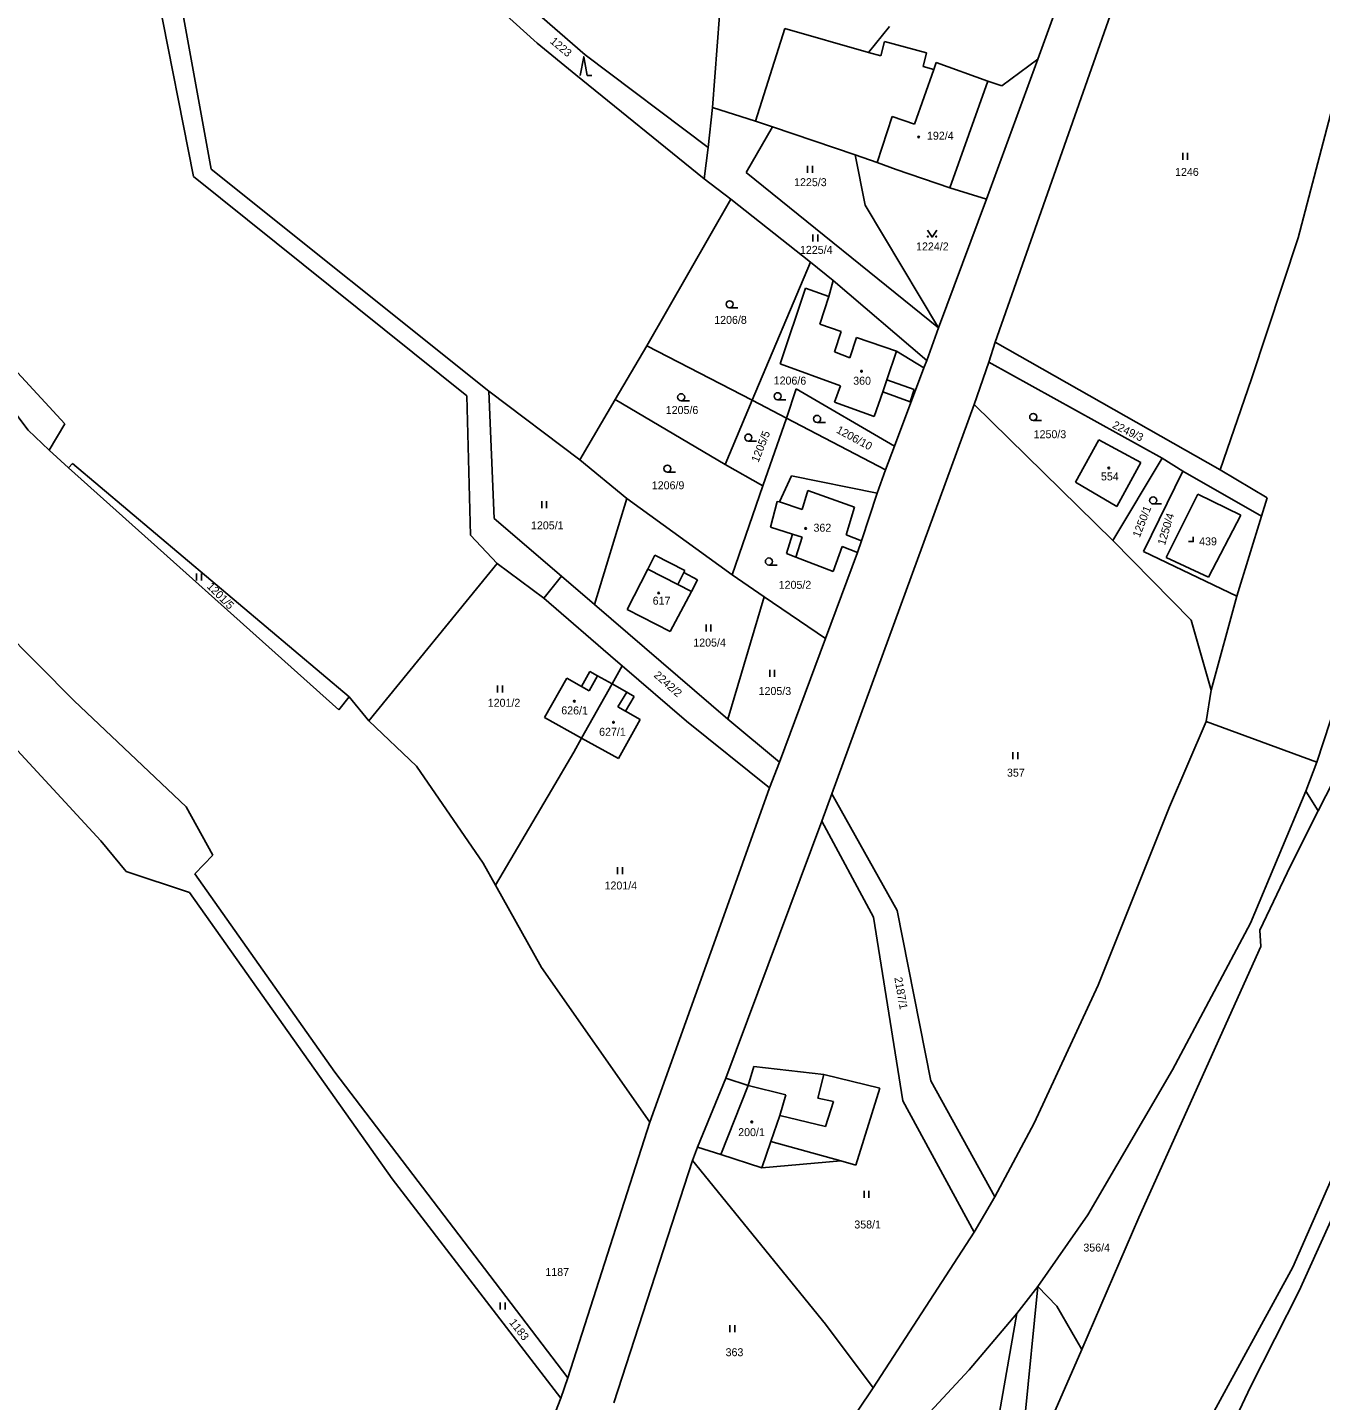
# Model space of a CAD drawing. Extents: x -717507 to -715515, y -957700 to -954941.
# Drawn here: x -717129.5 to -716853.4, y -957227.8 to -956934.7 of the extents above; entities that cross this region are included whole.
import ezdxf

# ---------------------------------------------------------------- set-up
doc = ezdxf.new("R2010")
doc.units = 0
for name, color, linetype in [('Hranice parcel', 7, 'Continuous'), ('Parcelní čísla', 7, 'Continuous'), ('Vnitřní kresba', 7, 'Continuous'), ('Značky budov', 7, 'Continuous'), ('Značky kultur', 7, 'Continuous')]:
    doc.layers.add(name, color=color, linetype=linetype)

msp = doc.modelspace()

# ---------------------------------------------------------------- linework, layer by layer
at = {"layer": 'Hranice parcel'}
for points in [[(-716883.47, -956889.98), (-716922.85, -957001.88)], [(-716899.47, -956902.24), (-716913.71, -956941.41)], [(-717040.64, -956914.21), (-717010.38, -956940.53)], [(-717020.68, -956938), (-717043.43, -956917.39)], [(-717090.31, -956964.95), (-717097.11, -956927.29)], [(-716983.22, -956951.73), (-716981.19, -956925.52)], [(-717101.64, -956927.88), (-717094.06, -956966.51)], [(-716967.79, -956934.88), (-716974.01, -956954.65)], [(-716967.79, -956934.88), (-716949.89, -956940.04)], [(-716949.89, -956940.04), (-716945.43, -956934.46)], [(-717012.39, -956944.75), (-717020.68, -956938)], [(-716946.46, -956937.68), (-716947.27, -956940.76)], [(-716946.46, -956937.68), (-716937.49, -956940.07)], [(-716984.16, -956960.33), (-717010.38, -956940.53)], [(-716949.89, -956940.04), (-716947.27, -956940.76)], [(-716937.49, -956940.07), (-716938.2, -956943.02)], [(-716924.72, -956971.35), (-716913.71, -956941.41)], [(-716913.71, -956941.41), (-716921.45, -956947.14)], [(-716985.03, -956966.96), (-717012.39, -956944.75)], [(-716938.2, -956943.02), (-716935.96, -956943.61)], [(-716935.48, -956942.18), (-716935.96, -956943.61)], [(-716935.48, -956942.18), (-716924.4, -956946.14)], [(-716924.4, -956946.14), (-716921.45, -956947.14)], [(-716849.73, -956947.55), (-716858.15, -956979.57)], [(-716983.22, -956951.73), (-716984.16, -956960.33)], [(-716983.22, -956951.73), (-716974.01, -956954.65)], [(-716976.05, -956965.65), (-716970.44, -956955.86)], [(-716974.01, -956954.65), (-716970.44, -956955.86)], [(-716970.44, -956955.86), (-716952.72, -956961.89)], [(-717175.29, -956959.79), (-717129.34, -957020.62)], [(-716984.16, -956960.33), (-716985.03, -956966.96)], [(-716952.72, -956961.89), (-716950.58, -956972.63)], [(-716952.72, -956961.89), (-716948.05, -956963.51)], [(-717031.01, -957012.35), (-717090.31, -956964.95)], [(-716948.05, -956963.51), (-716943.97, -956965)], [(-716943.97, -956965), (-716932.56, -956968.89)], [(-717094.06, -956966.51), (-717035.68, -957013.31)], [(-716985.03, -956966.96), (-716979.33, -956971.36)], [(-716934.96, -956998.81), (-716976.05, -956965.65)], [(-716997.26, -957002.63), (-716979.33, -956971.36)], [(-716979.33, -956971.36), (-716962.26, -956984.8)], [(-716924.72, -956971.35), (-716934.96, -956998.81)], [(-716932.56, -956968.89), (-716924.72, -956971.35)], [(-716934.96, -956998.81), (-716950.58, -956972.63)], [(-716858.15, -956979.57), (-716868.1, -957009.68)], [(-716962.26, -956984.8), (-716974.74, -957014.21)], [(-716962.26, -956984.8), (-716957.43, -956988.72)], [(-716958.39, -956992.1), (-716957.43, -956988.72)], [(-716957.43, -956988.72), (-716937.47, -957005.77)], [(-716963.33, -956990.31), (-716968.74, -957006.5)], [(-716963.33, -956990.31), (-716958.39, -956992.1)], [(-717121.57, -957019.32), (-717146.06, -956992.81)], [(-716934.96, -956998.81), (-716937.47, -957005.77)], [(-716997.26, -957002.63), (-717003.99, -957014.1)], [(-716997.26, -957002.63), (-716974.74, -957014.21)], [(-716922.85, -957001.88), (-716924.19, -957006.09)], [(-716922.85, -957001.88), (-716874.81, -957029.09)], [(-716968.74, -957006.5), (-716955.91, -957011.2)], [(-716943.95, -957003.75), (-716946, -957009.87)], [(-716938.06, -957007.35), (-716943.95, -957003.75)], [(-716937.47, -957005.77), (-716938.06, -957007.35)], [(-716924.19, -957006.09), (-716927.36, -957015.18)], [(-716924.19, -957006.09), (-716887.2, -957026.59)], [(-716938.06, -957007.35), (-716944.34, -957024.03)], [(-717011.58, -957027), (-717031.01, -957012.35)], [(-717029.86, -957039.5), (-717031.01, -957012.35)], [(-716965.34, -957011.84), (-716967.45, -957018.1)], [(-716944.34, -957024.03), (-716965.34, -957011.84)], [(-716955.91, -957011.2), (-716957.14, -957014.7)], [(-716946.87, -957012.44), (-716948.72, -957017.75)], [(-716946.87, -957012.44), (-716941.01, -957014.57)], [(-716946, -957009.87), (-716940.13, -957011.95)], [(-716940.13, -957011.95), (-716941.01, -957014.57)], [(-716874.81, -957029.09), (-716868.1, -957009.68)], [(-717035.68, -957013.31), (-717034.88, -957043.03)], [(-717003.99, -957014.1), (-717011.58, -957027)], [(-717003.99, -957014.1), (-716980.54, -957027.95)], [(-716974.74, -957014.21), (-716980.54, -957027.95)], [(-716974.74, -957014.21), (-716967.45, -957018.1)], [(-716927.36, -957015.18), (-716957.76, -957098.3)], [(-716957.14, -957014.7), (-716948.72, -957017.75)], [(-716927.36, -957015.18), (-716897.7, -957044.17)], [(-716967.45, -957018.1), (-716972.5, -957032.52)], [(-716967.45, -957018.1), (-716946.29, -957029.08)], [(-717124.87, -957024.92), (-717129.34, -957020.62)], [(-717121.57, -957019.32), (-717124.87, -957024.92)], [(-716944.34, -957024.03), (-716946.29, -957029.08)], [(-716900.69, -957022.74), (-716905.7, -957031.72)], [(-716900.69, -957022.74), (-716891.72, -957027.57)], [(-717120.72, -957028.71), (-717124.87, -957024.92)], [(-717001.53, -957035.23), (-717011.58, -957027)], [(-716887.2, -957026.59), (-716897.7, -957044.17)], [(-716887.2, -957026.59), (-716882.75, -957029.4)], [(-717120.72, -957028.71), (-717119.88, -957027.74)], [(-717062.99, -957080.37), (-717120.72, -957028.71)], [(-717060.78, -957077.58), (-717119.88, -957027.74)], [(-716980.54, -957027.95), (-716972.5, -957032.52)], [(-716946.29, -957029.08), (-716948.04, -957034.12)], [(-716891.72, -957027.57), (-716896.85, -957036.91)], [(-716882.75, -957029.4), (-716891.17, -957046.55)], [(-716882.75, -957029.4), (-716865.96, -957038.98)], [(-716874.81, -957029.09), (-716864.74, -957035.09)], [(-716972.5, -957032.52), (-716978.99, -957051.55)], [(-716966.38, -957030.36), (-716968.94, -957035.94)], [(-716966.38, -957030.36), (-716948.04, -957034.12)], [(-716905.7, -957031.72), (-716896.85, -957036.91)], [(-717008.45, -957057.86), (-717001.53, -957035.23)], [(-716978.99, -957051.55), (-717001.53, -957035.23)], [(-716969.39, -957035.84), (-716970.81, -957041.37)], [(-716969.39, -957035.84), (-716968.94, -957035.94)], [(-716948.04, -957034.12), (-716951.4, -957044.29)], [(-716879.57, -957034.34), (-716886.33, -957047.83)], [(-716879.57, -957034.34), (-716870.36, -957038.79)], [(-716864.74, -957035.09), (-716865.96, -957038.98)], [(-716870.36, -957038.79), (-716877.32, -957052.05)], [(-717015.46, -957051.8), (-717029.86, -957039.5)], [(-716970.81, -957041.37), (-716966.11, -957042.83)], [(-716865.96, -957038.98), (-716871.21, -957056.08)], [(-717034.88, -957043.03), (-717029.19, -957049.13)], [(-716966.11, -957042.83), (-716967.41, -957046.98)], [(-716951.4, -957044.29), (-716952.24, -957046.75)], [(-716897.7, -957044.17), (-716880.98, -957061.2)], [(-716995.51, -957047.35), (-716997.02, -957050.3)], [(-716995.51, -957047.35), (-716989.12, -957050.63)], [(-716967.41, -957046.98), (-716965.4, -957047.72)], [(-716952.24, -957046.75), (-716959.08, -957065.13)], [(-716955.52, -957045.49), (-716957.43, -957050.8)], [(-716955.52, -957045.49), (-716952.24, -957046.75)], [(-716891.17, -957046.55), (-716871.21, -957056.08)], [(-717029.19, -957049.13), (-717056.63, -957082.7)], [(-717029.19, -957049.13), (-717019.23, -957056.54)], [(-716997.02, -957050.3), (-717001.45, -957058.93)], [(-716965.4, -957047.72), (-716957.43, -957050.8)], [(-716886.33, -957047.83), (-716877.32, -957052.05)], [(-717018.6, -957055.75), (-717015.46, -957051.8)], [(-717008.45, -957057.86), (-717015.46, -957051.8)], [(-716989.12, -957050.63), (-716989.34, -957051.06)], [(-716989.34, -957051.06), (-716986.41, -957052.56)], [(-716986.41, -957052.56), (-716987.7, -957055.08)], [(-716972.18, -957056.21), (-716978.99, -957051.55)], [(-716854.19, -957091.5), (-716841.23, -957052.04)], [(-717119.57, -957078.45), (-717143.05, -957054.83)], [(-717018.6, -957055.75), (-717019.23, -957056.54)], [(-716987.7, -957055.08), (-716992.26, -957063.64)], [(-716979.94, -957082.35), (-716972.18, -957056.21)], [(-716959.08, -957065.13), (-716972.18, -957056.21)], [(-716871.21, -957056.08), (-716876.69, -957076.13)], [(-717019.23, -957056.54), (-717003.9, -957069.75)], [(-716979.94, -957082.35), (-717008.45, -957057.86)], [(-717001.45, -957058.93), (-716992.26, -957063.64)], [(-716876.69, -957076.13), (-716880.98, -957061.2)], [(-716959.08, -957065.13), (-716968.89, -957091.5)], [(-716834.54, -957064.04), (-716853.87, -957101.91)], [(-717002.5, -957070.96), (-717004.65, -957074.83)], [(-717003.9, -957069.75), (-717002.5, -957070.96)], [(-717002.5, -957070.96), (-716988.77, -957082.77)], [(-717014.35, -957073.57), (-717019.09, -957081.99)], [(-717011.18, -957075.35), (-717014.35, -957073.57)], [(-717009.41, -957072.18), (-717011.18, -957075.35)], [(-717007.79, -957073.08), (-717009.41, -957072.18)], [(-717007.79, -957073.08), (-717004.65, -957074.83)], [(-717004.65, -957074.83), (-717011.17, -957086.38)], [(-717001.54, -957076.57), (-717004.65, -957074.83)], [(-716999.92, -957077.47), (-717001.54, -957076.57)], [(-716876.69, -957076.13), (-716877.77, -957082.81)], [(-717095.65, -957101.03), (-717119.57, -957078.45)], [(-717060.78, -957077.58), (-717062.99, -957080.37)], [(-717060.78, -957077.58), (-717056.63, -957082.7)], [(-717001.79, -957080.62), (-716999.92, -957077.47)], [(-717046.43, -957092.34), (-717056.63, -957082.7)], [(-717019.09, -957081.99), (-717011.17, -957086.38)], [(-717003.27, -957090.76), (-716998.65, -957082.38)], [(-716998.65, -957082.38), (-717001.79, -957080.62)], [(-716988.77, -957082.77), (-716971.07, -957097)], [(-716968.89, -957091.5), (-716979.94, -957082.35)], [(-716877.77, -957082.81), (-716885.65, -957101.08)], [(-716877.77, -957082.81), (-716854.19, -957091.5)], [(-717136.81, -957083.48), (-717113.86, -957108.34)], [(-717011.17, -957086.38), (-717012.83, -957089.39)], [(-717011.17, -957086.38), (-717003.27, -957090.76)], [(-717012.83, -957089.39), (-717017.59, -957097.48)], [(-716971.07, -957097), (-716968.89, -957091.5)], [(-716856.5, -957097.71), (-716854.19, -957091.5)], [(-717046.43, -957092.34), (-717032.22, -957113.08)], [(-717017.59, -957097.48), (-717029.57, -957117.8)], [(-716982.61, -957129.3), (-716971.07, -957097)], [(-716957.76, -957098.3), (-716959.9, -957104.09)], [(-716957.76, -957098.3), (-716943.77, -957123.22)], [(-716868.32, -957125.9), (-716856.5, -957097.71)], [(-716853.87, -957101.91), (-716856.5, -957097.71)], [(-717095.65, -957101.03), (-717089.96, -957111.41)], [(-716900.87, -957139.14), (-716885.65, -957101.08)], [(-716853.87, -957101.91), (-716859.8, -957113.63)], [(-716959.9, -957104.09), (-716980.38, -957159)], [(-716959.9, -957104.09), (-716948.82, -957124.63)], [(-717108.43, -957114.88), (-717113.86, -957108.34)], [(-717089.96, -957111.41), (-717093.74, -957115.35)], [(-717108.43, -957114.88), (-717094.88, -957119.36)], [(-717032.22, -957113.08), (-717029.57, -957117.8)], [(-716859.8, -957113.63), (-716866.3, -957127.42)], [(-717093.74, -957115.35), (-717063.87, -957157.69)], [(-717019.75, -957135.34), (-717029.57, -957117.8)], [(-716859.27, -957199.3), (-716823.29, -957117.25)], [(-717094.88, -957119.36), (-717051.63, -957180.5)], [(-716943.77, -957123.22), (-716936.58, -957159.52)], [(-716948.82, -957124.63), (-716942.54, -957163.79)], [(-716884.96, -957157.2), (-716868.32, -957125.9)], [(-716996.57, -957168.36), (-716982.61, -957129.3)], [(-716866.3, -957127.42), (-716866.09, -957130.84)], [(-716823.97, -957129.29), (-716857.93, -957204.39)], [(-716866.09, -957130.84), (-716892.17, -957188.76)], [(-716996.57, -957168.36), (-717019.75, -957135.34)], [(-716900.87, -957139.14), (-716914.54, -957168.6)], [(-717014.14, -957222.99), (-717063.87, -957157.69)], [(-716980.38, -957159), (-716986.4, -957173.71)], [(-716980.38, -957159), (-716975.62, -957160.52)], [(-716974.36, -957156.51), (-716975.62, -957160.52)], [(-716974.36, -957156.51), (-716959.41, -957158.22)], [(-716947.51, -957161.09), (-716959.41, -957158.22)], [(-716903.08, -957188.17), (-716884.96, -957157.2)], [(-716947.51, -957161.09), (-716952.58, -957177.57)], [(-716922.9, -957184.34), (-716936.58, -957159.52)], [(-716927.37, -957191.86), (-716942.54, -957163.79)], [(-716996.57, -957168.36), (-717014.14, -957222.99)], [(-716914.54, -957168.6), (-716922.9, -957184.34)], [(-716986.4, -957173.71), (-716987.46, -957176.58)], [(-716986.4, -957173.71), (-716981.47, -957175.31)], [(-716987.46, -957176.58), (-717004.3, -957228.3)], [(-716987.46, -957176.58), (-716959.12, -957211.47)], [(-716981.47, -957175.31), (-716972.71, -957178.12)], [(-716972.71, -957178.12), (-716955.82, -957176.65)], [(-716955.82, -957176.65), (-716952.58, -957177.57)], [(-717051.63, -957180.5), (-717015.58, -957227.31)], [(-716922.9, -957184.34), (-716927.37, -957191.86)], [(-716903.08, -957188.17), (-716913.74, -957203.47)], [(-716892.17, -957188.76), (-716904.33, -957216.92)], [(-716927.37, -957191.86), (-716948.88, -957225.08)], [(-716859.27, -957199.3), (-716896.13, -957266.78)], [(-716913.74, -957203.47), (-716918.24, -957209.2)], [(-716913.74, -957203.47), (-716909.66, -957207.64)], [(-716868.3, -957224.89), (-716857.93, -957204.39)], [(-716904.33, -957216.92), (-716909.66, -957207.64)], [(-716948.88, -957225.08), (-716959.12, -957211.47)], [(-716918.24, -957209.2), (-716928.37, -957221.22)], [(-716918.24, -957209.2), (-716921.9, -957230.38)], [(-716904.33, -957216.92), (-716932.34, -957280.9)], [(-717014.14, -957222.99), (-717015.58, -957227.31)], [(-716972.18, -957268.34), (-716928.37, -957221.22)], [(-716961.32, -957243.51), (-716948.88, -957225.08)], [(-716883.16, -957256.29), (-716868.3, -957224.89)], [(-717042.82, -957297.1), (-717015.58, -957227.31)]]:
    msp.add_lwpolyline(points, dxfattribs=at)
at = {"layer": 'Vnitřní kresba'}
for points in [[(-716935.96, -956943.61), (-716940.05, -956955.34)], [(-716924.4, -956946.14), (-716932.56, -956968.89)], [(-716944.87, -956953.65), (-716948.05, -956963.51)], [(-716944.87, -956953.65), (-716940.05, -956955.34)], [(-716958.39, -956992.1), (-716960.28, -956998.02)], [(-716960.28, -956998.02), (-716955.72, -956999.57)], [(-716955.72, -956999.57), (-716957.14, -957003.95)], [(-716952.48, -957000.83), (-716953.87, -957005.18)], [(-716952.48, -957000.83), (-716943.95, -957003.75)], [(-716957.14, -957003.95), (-716953.87, -957005.18)], [(-716946, -957009.87), (-716946.87, -957012.44)], [(-716968.94, -957035.94), (-716964.1, -957037.61)], [(-716964.1, -957037.61), (-716962.84, -957033.5)], [(-716962.84, -957033.5), (-716952.89, -957037.06)], [(-716952.89, -957037.06), (-716954.67, -957043.02)], [(-716966.11, -957042.83), (-716964.1, -957043.51)], [(-716964.1, -957043.51), (-716965.4, -957047.72)], [(-716954.67, -957043.02), (-716951.4, -957044.29)], [(-716997.02, -957050.3), (-716990.63, -957053.58)], [(-716990.63, -957053.58), (-716989.34, -957051.06)], [(-716990.63, -957053.58), (-716987.7, -957055.08)], [(-717009.56, -957076.26), (-717007.79, -957073.08)], [(-717011.18, -957075.35), (-717009.56, -957076.26)], [(-717001.54, -957076.57), (-717003.41, -957079.71)], [(-717003.41, -957079.71), (-717001.79, -957080.62)], [(-716959.41, -957158.22), (-716960.69, -957163.23)], [(-716975.62, -957160.52), (-716981.47, -957175.31)], [(-716975.62, -957160.52), (-716967.53, -957162.56)], [(-716967.53, -957162.56), (-716968.87, -957166.95)], [(-716960.69, -957163.23), (-716957.4, -957163.96)], [(-716957.4, -957163.96), (-716959.11, -957169.33)], [(-716968.87, -957166.95), (-716970.76, -957172.5)], [(-716968.87, -957166.95), (-716959.11, -957169.33)], [(-716970.76, -957172.5), (-716972.71, -957178.12)], [(-716970.76, -957172.5), (-716955.82, -957176.65)], [(-716913.74, -957203.47), (-716916.53, -957231.47)]]:
    msp.add_lwpolyline(points, dxfattribs=at)
at = {"layer": 'Značky budov'}
for centre in [(-716939.18, -956958.06), (-716951.4, -957008.06), (-716898.59, -957028.72), (-716963.31, -957041.63), (-716994.71, -957055.4), (-717012.73, -957078.51), (-717004.36, -957083.01), (-716974.83, -957168.31)]:
    msp.add_circle(centre, 0.175, dxfattribs=at)
at = {"layer": 'Značky kultur'}
for points in [[(-717011.46, -956944.91), (-717010.71, -956940.91), (-717009.96, -956944.91), (-717008.96, -956944.91)], [(-716882.79, -956962.93), (-716882.79, -956961.43)], [(-716881.75, -956962.93), (-716881.75, -956961.43)], [(-716962.91, -956965.74), (-716962.91, -956964.24)], [(-716961.87, -956965.74), (-716961.87, -956964.24)], [(-716961.76, -956980.34), (-716961.76, -956978.84)], [(-716960.72, -956980.34), (-716960.72, -956978.84)], [(-716937.32, -956977.92), (-716936.32, -956979.42), (-716935.32, -956977.92)], [(-716979.56, -956994.51), (-716977.81, -956994.51)], [(-716989.91, -957014.36), (-716988.16, -957014.36)], [(-716969.31, -957014.14), (-716967.56, -957014.14)], [(-716960.87, -957018.98), (-716959.12, -957018.98)], [(-716914.73, -957018.58), (-716912.98, -957018.58)], [(-716975.58, -957022.97), (-716973.83, -957022.97)], [(-716992.85, -957029.61), (-716991.1, -957029.61)], [(-717019.7, -957037.31), (-717019.7, -957035.81)], [(-717018.66, -957037.31), (-717018.66, -957035.81)], [(-716889.11, -957036.4), (-716887.36, -957036.4)], [(-716881.55, -957044.43), (-716880.55, -957044.43), (-716880.55, -957043.43)], [(-716971.18, -957049.43), (-716969.43, -957049.43)], [(-717093.41, -957052.74), (-717093.41, -957051.24)], [(-717092.37, -957052.74), (-717092.37, -957051.24)], [(-716984.6, -957063.65), (-716984.6, -957062.15)], [(-716983.56, -957063.65), (-716983.56, -957062.15)], [(-716970.99, -957073.3), (-716970.99, -957071.8)], [(-716969.95, -957073.3), (-716969.95, -957071.8)], [(-717029.13, -957076.65), (-717029.13, -957075.15)], [(-717028.09, -957076.65), (-717028.09, -957075.15)], [(-716919.05, -957090.9), (-716919.05, -957089.4)], [(-716918.01, -957090.9), (-716918.01, -957089.4)], [(-717003.49, -957115.46), (-717003.49, -957113.96)], [(-717002.45, -957115.46), (-717002.45, -957113.96)], [(-716950.85, -957184.51), (-716950.85, -957183.01)], [(-716949.81, -957184.51), (-716949.81, -957183.01)], [(-717028.56, -957208.34), (-717028.56, -957206.84)], [(-717027.53, -957208.34), (-717027.53, -957206.84)], [(-716979.51, -957213.19), (-716979.51, -957211.69)], [(-716978.47, -957213.19), (-716978.47, -957211.69)]]:
    msp.add_lwpolyline(points, dxfattribs=at)
for centre, radius in [((-716937.22, -956979.32), 0.1), ((-716935.42, -956979.32), 0.1), ((-716979.56, -956993.76), 0.75), ((-716989.91, -957013.61), 0.75), ((-716969.31, -957013.39), 0.75), ((-716960.87, -957018.23), 0.75), ((-716914.73, -957017.83), 0.75), ((-716975.58, -957022.22), 0.75), ((-716992.85, -957028.86), 0.75), ((-716889.11, -957035.65), 0.75), ((-716971.18, -957048.68), 0.75)]:
    msp.add_circle(centre, radius, dxfattribs=at)

# ---------------------------------------------------------------- texts
at = {"layer": 'Parcelní čísla'}
for s, rotation, p in [('1223', 320.0025, (-717018.04, -956937.85)), ('1206/6', 359.4029, (-716970.16, -957010.87)), ('1205/5', 68.4005, (-716973.42, -957027.66)), ('1206/10', 331.7026, (-716956.93, -957021.09)), ('2249/3', 334.1027, (-716897.97, -957020.08)), ('1250/1', 68.8005, (-716891.99, -957043.7)), ('1250/4', 73.1006, (-716886.6, -957045.33)), ('1201/5', 315.0025, (-717091.34, -957054.13)), ('2242/2', 318.6025, (-716995.89, -957073.16)), ('626/1', 359.5029, (-717015.52, -957081.3)), ('2187/1', 280.0022, (-716944.4, -957137.55)), ('1183', 308.1674, (-717026.73, -957211.18))]:
    msp.add_text(s, height=1.7, rotation=rotation, dxfattribs=at).set_placement(p)
for s, p in [('192/4', (-716937.41, -956958.63)), ('1246', (-716884.43, -956966.36)), ('1225/3', (-716965.79, -956968.55)), ('1225/4', (-716964.54, -956983)), ('1224/2', (-716939.74, -956982.27)), ('1206/8', (-716982.85, -956997.95)), ('360', (-716953.17, -957010.94)), ('1205/6', (-716993.2, -957017.19)), ('1250/3', (-716914.63, -957022.36)), ('554', (-716900.26, -957031.37)), ('1206/9', (-716996.18, -957033.26)), ('1205/1', (-717021.98, -957041.82)), ('362', (-716961.65, -957042.32)), ('439', (-716879.29, -957045.23)), ('1205/2', (-716969.08, -957054.51)), ('617', (-716995.99, -957057.9)), ('1205/4', (-716987.32, -957066.84)), ('1205/3', (-716973.37, -957077.18)), ('1201/2', (-717031.22, -957079.69)), ('627/1', (-717007.43, -957085.89)), ('357', (-716920.33, -957094.61)), ('1201/4', (-717006.27, -957118.7)), ('200/1', (-716977.73, -957171.36)), ('358/1', (-716952.93, -957191.07)), ('356/4', (-716904.01, -957196)), ('1187', (-717018.91, -957201.21)), ('363', (-716980.42, -957218.34))]:
    msp.add_text(s, height=1.7, dxfattribs=at).set_placement(p)

doc.saveas('drawing.dxf')
